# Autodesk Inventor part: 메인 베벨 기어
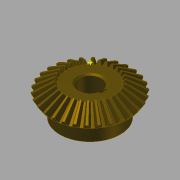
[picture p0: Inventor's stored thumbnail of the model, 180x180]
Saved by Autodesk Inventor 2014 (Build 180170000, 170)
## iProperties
Created: 2014-10
Part Number: 메인 베벨 기어
Material: 강철, 탄소
Document SubType Name: Modeling
Designer: KYOUNG IL JANG
Categories: <?xml version="1.0" encoding="UTF-16"?> <MemberInstance><Categories><FamilyTemplate><FamilyTemplateParameter ValueType="xs:double" Id="1" ObjectReferenceKey="da
Mass: 269.926 g
Surface Area: 108.837 cm^2
Volume: 34.2981 cm^3
Density: 7.87 g/cm^3
Appearance: 얼룩무늬
CustomPartVersion: 1
Author: SeoGD™ [www.esajin.kr]
Revision Number: 1
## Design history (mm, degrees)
node "맨 위 점"
node "메쉬 평면2"
sketch "톱니 본체 스케치"
  geometry: L1 (0, 0)-(28.669, -21.997); L2 (28.669, -21.997)-(31.109, -18.336); L3 (31.109, -18.336)-(0, 0); L4 (30, -20)-(0, 0); L5 (17.219, -13.212)-(18.685, -11.013); L6 (28.669, -21.997)-(17.219, -13.212); L7 (31.109, -18.336)-(18.685, -11.013); L8 (0, -39.387)-(0, 6.564) reference; L9 (0, -20)-(31.109, -20)
  constraints: 16 end point, 4 point on line, 3 perpendicular, 2 collinear, 1 horizontal alignment, 1 vertical alignment
  dimensions: "d0" = 60 diameter of L4.start L8 (= da_de); "d1" = 57.33744 diameter of L1.end L8 (= da_dfe); "d2" = 62.2188 diameter of L2.end L8 (= da_dae); "d3" = 14.4 distance between parallel lines of L2 L5 (= da_b); "d4" = 18.3359 vertical distance of L2.end L1.start (= da_ve)
revolve "톱니 본체" sketch "톱니 본체 스케치" stored, may be unused: angle "d5" = 90 deg
node "시작점"
node "톱니 평면"
sketch "시작 스케치"
  geometry: L1 (0, -23.505)-(0, 10.645) reference; L2 (-0.709, -2.928)-(0.709, -2.928); A1 r 19.188 centre (-19.457, -7.014) between (-0.709, -2.928) and (-3.232, 3.229); A2 r 19.188 centre (19.457, -7.014) between (3.232, 3.229) and (0.709, -2.928); A3 r 57.403 centre (0, -54.083) between (3.232, 3.229) and (-3.232, 3.229); 1 further point
  constraints: 6 point on circle, 3 centre point, 3 symmetric about line, 2 end point, 1 coincident, 1 perpendicular, 1 other
  dimensions: "d7" = 19.18795 radius of A1 (= fd_rr); "d8" = 19.45712 horizontal distance of point (0, -54.083) A1.centre (= fd_x); "d9" = 47.06905 vertical distance of point (0, -54.083) A1.centre (= fd_y); "d57" = 57.40327 radius of A3 (= 0.5 x fd_dva + 0.3 x da_he); "d58" = 51.15527 distance from line of A3.centre L2 (= 0.5 x fd_dva - 1.12 x da_he)
node "끝점"
  node "끝 평면"
sketch "3D 스케치 오른쪽"
  node "Helical Curve Right" dims "d65" = 229.90621 (computed from da_dm, da_delta, da_beta), "d66" = 31.5, "d67" = 60 (= da_de), "d68" = -9.82794 (= -da_delta), "d69" = 8.10972 (computed from fd_loft, da_delta)
node "끝 평면 오른쪽"
sketch "끝 스케치 오른쪽"
  geometry: L1 (0, -41.54)-(0, 13.178) reference; L2 (-0.422, -1.69)-(0.422, -1.69); A1 r 11.427 centre (-11.587, -4.123) between (-0.422, -1.69) and (-1.925, 1.977); A2 r 11.427 centre (11.587, -4.123) between (1.925, 1.977) and (0.422, -1.69); A3 r 34.184 centre (0, -32.153) between (1.925, 1.977) and (-1.925, 1.977); 1 further point
  constraints: 6 point on circle, 3 centre point, 3 symmetric about line, 2 end point, 1 coincident, 1 perpendicular, 1 other
  dimensions: "d70" = 11.58699 horizontal distance of A3.centre A1.centre (computed from fd_x, fd_ratio); "d71" = 28.03028 vertical distance of point (0, -32.153) A1.centre (computed from fd_y, fd_ratio); "d72" = 11.4267 radius of A1 (computed from fd_rr, fd_ratio); "d73" = 30.46369 distance from line of point (0, -32.153) L2 (computed from d58, fd_ratio); "d74" = 34.18446 radius of A3 (computed from d57, fd_ratio)
feature "로프트 오른쪽" sketch "끝 스케치 오른쪽" dims "d75" = 0, "d77" = 0, "d79" = 0, "d80" = 90 deg, "d85" = 20, "d92" = 90 deg, "d93" = 90 deg, "da_teethtype" = 0 [user parameter]
sketch "3D 스케치 왼쪽"
  node "Helical Curve Left" dims "d26" = 229.90621 (computed from da_dm, da_delta, da_beta), "d27" = 8.10972 (computed from fd_loft, da_delta), "d28" = 60 (= da_de), "d29" = -9.82794 (= -da_delta)
node "끝 평면 왼쪽"
sketch "끝 스케치 왼쪽" dims "d56" = 10.3728 (derived)
  geometry: L1 (0, -43.753)-(0, 15.405) reference; L2 (-0.422, -1.678)-(0.422, -1.678); A1 r 11.427 centre (-11.587, -4.111) between (-0.422, -1.678) and (-1.925, 1.988); A2 r 11.427 centre (11.587, -4.111) between (1.925, 1.988) and (0.422, -1.678); A3 r 34.184 centre (0, -32.142) between (1.925, 1.988) and (-1.925, 1.988); 2 further points; 1 other entity
  constraints: 6 point on circle, 3 centre point, 3 symmetric about line, 2 end point, 1 coincident, 2 other
  dimensions: "d30" = 11.4267 radius of A1 (computed from fd_rr, fd_ratio); "d31" = 11.58699 horizontal distance of point (0, -32.142) A1.centre (computed from fd_x, fd_ratio); "d32" = 28.03028 vertical distance of A1.centre point (0, -32.142) (computed from fd_y, fd_ratio); "d61" = 34.18446 radius of A3 (computed from d57, fd_ratio); "d62" = 30.46369 distance from line of point (0, -32.142) L2 (computed from d58, fd_ratio)
feature "로프트 왼쪽" sketch "끝 스케치 왼쪽" dims "d35" = 0, "d37" = 0, "d39" = 0, "d40" = 90 deg, "d84" = 10, "d90" = 90 deg, "d91" = 90 deg, "da_teethtype" = 0 [user parameter]
sketch "본체 스케치"
  geometry: L1 (0, -35.038)-(0, -19.531) reference; L2 (28.669, -21.997)-(17.219, -13.212) reference; L3 (17.219, -13.212)-(0, -13.212); L4 (28.669, -21.997)-(0, -21.997)
  constraints: 4 end point, 2 perpendicular, 2 point on line
revolve "본체 고정" sketch "본체 스케치" stored, may be unused: angle "d46" = 90 deg
feature "피치 지름" dims angle "d47" = 90 deg
sketch "스케치8"
  geometry: C1 r 22.5 at (0, 0); 1 further point
  constraints: 1 centre point, 1 coincident
  dimensions: "d94" = 45 diameter of C1
extrude "돌출1" join sketch "스케치8" distance "d95" = 13; taper "d96" = 0 deg
sketch "스케치9"
  geometry: 1 further point
hole "구멍1" sketch "스케치9" at (0, 0) diameter "d97" = 17; stored, may be unused: countersink angle "d101" = 90 deg, drill point angle "d103" = 118 deg; dims "d98" = 6, "d99" = 4, "d100" = 2, "d102" = 8
sketch "스케치10"
  geometry: L1 (8.124, 2.5)-(10.8, 2.5); L2 (10.8, 2.5)-(10.8, -2.5); L3 (10.8, -2.5)-(8.124, -2.5); A1 r 8.5 centre (0, 0) between (8.124, 2.5) and (8.124, -2.5) reference; 1 further point
  constraints: 6 end point, 2 parallel, 2 point on circle, 1 horizontal, 1 perpendicular
  dimensions: "d104" = 5 distance of L1.end L2.end; "d112" = 19.3 dimension on A1 L2
extrude "돌출2" cut sketch "스케치10" stored distance "d106" = 10; taper "d107" = 0 deg
chamfer "모따기1" distance "d108" = 1; stored, may be unused: second distance "d109" = 2, angle "d110" = 45 deg
fillet "모깎기1" dims "d111" = 2
body "Solid1"
feature "로프트" dims "d17" = 0, "d18" = 90 deg, "d19" = 0, "d20" = 90 deg, "d89" = 0, "da_teethtype" = 0 [user parameter]
pattern_circular "원형 패턴" dims angle "d22" = 360 deg, "d88" = 0, "da_teethtype" = 0 [user parameter]
pattern_circular "원형 패턴 오른쪽" dims angle "d82" = 360 deg, "da_teethtype" = 0 [user parameter]
pattern_circular "원형 패턴 왼쪽" dims angle "d42" = 360 deg, "da_teethtype" = 0 [user parameter]
sketch "끝 스케치"
  geometry: L1 (0, -15.359)-(0, 6.983) reference; L2 (-0.422, -1.69)-(0.422, -1.69); A1 r 11.427 centre (-11.587, -4.123) between (-0.422, -1.69) and (-1.925, 1.977); A2 r 11.427 centre (11.587, -4.123) between (1.925, 1.977) and (0.422, -1.69); A3 r 34.184 centre (0, -32.153) between (1.925, 1.977) and (-1.925, 1.977); 1 further point
  constraints: 6 point on circle, 3 centre point, 3 symmetric about line, 2 end point, 1 coincident, 1 other
  dimensions: "d12" = 11.4267 radius of A1 (computed from fd_rr, fd_ratio); "d15" = 11.58699 horizontal distance of A1.centre point (0, -32.153) (computed from fd_x, fd_ratio); "d16" = 28.03028 vertical distance of A1.centre point (0, -32.153) (computed from fd_y, fd_ratio); "d59" = 34.18446 radius of A3 (computed from d57, fd_ratio); "d60" = 30.46369 distance from line of A3.centre L2 (computed from d58, fd_ratio)
sketch "Sketch6"
  geometry: L1 (30, -20)-(0, 0) reference; L2 (0, -37.8)-(0, 6.3) reference
body "Srf1"
other parameters: "da_b" = 14.4 [user parameter; used in 2 equation terms], "da_de" = 60 [user parameter; used in 4 equation terms], "da_dae" = 62.2188 [user parameter; used in 2 equation terms], "da_dfe" = 57.33744 [user parameter; used in 1 equation term], "da_le" = 36.05551 [user parameter; used in 1 equation term], "da_omega" = 90 deg [user parameter; used in 1 equation term], "da_beta" = 0 [user parameter; used in 2 equation terms], "da_delta" = 9.82794 [user parameter; used in 8 equation terms], "da_alpha" = 20 deg [user parameter; used in 2 equation terms], "da_he" = 4.4 [user parameter; used in 4 equation terms], "da_ve" = 18.3359 [user parameter; used in 1 equation term], "fd_dv" = 108.16654 (computed from da_de, da_delta) [user parameter; used in 1 equation term], "fd_dva" = 112.16654 (computed from da_dae, da_delta) [user parameter; used in 3 equation terms], "fd_dvb" = 101.6433 (computed from fd_dv, da_alpha) [user parameter; used in 2 equation terms], "da_zv" = 540.83269 [user parameter; used in 1 equation term], "fd_loft" = 14.62 (= da_b + 0.05 x da_he) [user parameter; used in 4 equation terms], "fd_ratio" = 5.95514 (computed from da_le, fd_loft) [user parameter; used in 15 equation terms], "fd_rr" = 19.18795 (computed from fd_dd, fd_dvb) [user parameter; used in 6 equation terms], "fd_angle" = 0.29367 (computed from da_zv) [user parameter; used in 4 equation terms], "fd_x1" = 1.58802 (computed from da_dvw, fd_angle) [user parameter; used in 1 equation term], "fd_y1" = 54.05995 (computed from da_dvw, fd_angle) [user parameter; used in 1 equation term], "fd_x2" = 17.8691 (computed from fd_rr, fd_angle2, fd_angle) [user parameter; used in 1 equation term], "fd_y2" = 6.9909 (computed from fd_rr, fd_angle2, fd_angle) [user parameter; used in 1 equation term], "fd_x" = 19.45712 (= fd_x1 + fd_x2) [user parameter; used in 4 equation terms], "fd_y" = 47.06905 (= fd_y1 - fd_y2) [user parameter; used in 4 equation terms], "fd_angle2" = 3.43555 (computed from fd_dvb, fd_dd, da_alpha) [user parameter; used in 2 equation terms], "fd_dd" = 108.64654 (= fd_dva - 0.8 x da_he) [user parameter; used in 2 equation terms], "da_dvw" = 108.16654 [user parameter; used in 2 equation terms], "d11" = 14.62 (= fd_loft), "da_dm" = 48.01848 [user parameter; used in 2 equation terms], "da_x" = 0 [user parameter], "da_m" = 2 [user parameter], "d48" = 0, "d49" = 0, "d50" = 90 deg (= da_omega), "d51" = 6 deg (computed from da_z), "d52" = 0, "d53" = 0, "d54" = 0
